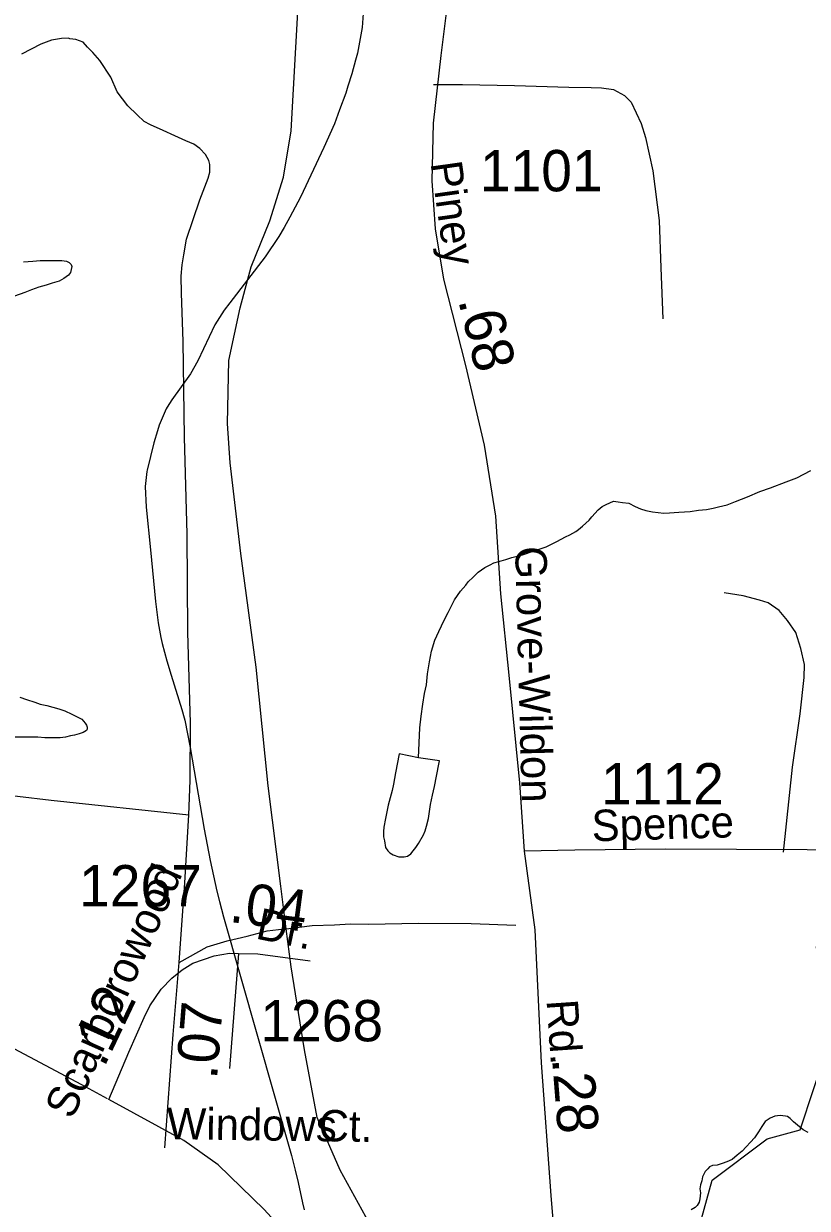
# Model space of a CAD drawing. Extents: x 2001466 to 2224147, y 644118 to 847247.
# Drawn here: x 2046028 to 2048402, y 675296 to 678885 of the extents above; entities that cross this region are included whole.
import ezdxf

# ---------------------------------------------------------------- set-up
doc = ezdxf.new("R2010")
doc.units = 0
for name, color, linetype in [('Exist Hydrographic Misc Water Feature', 7, 'Continuous'), ('Exist Railroad Mainline', 7, 'Continuous'), ('Exist Road Non-System Type 51', 7, 'Continuous'), ('Exist Road Secondary Mileage Hundredths English Label', 7, 'Continuous'), ('Exist Road Secondary Type 51 Attributed', 7, 'Continuous'), ('Exist Road Secondary Type 51 Label', 7, 'Continuous'), ('Exist Road Secondary Type 51 Number Label', 7, 'Continuous')]:
    doc.layers.add(name, color=color, linetype=linetype)

msp = doc.modelspace()

# ---------------------------------------------------------------- linework, layer by layer
at = {"layer": 'Exist Hydrographic Misc Water Feature'}
for p, q in [((2046652.9, 678039.2), (2046635.7, 678016.8)), ((2046463.1, 677723.6), (2046459.8, 677718.3)), ((2046402.8, 677532.5), (2046401.7, 677528.3)), ((2046873, 675313.1), (2046877.7, 675291.8))]:
    msp.add_line(p, q, dxfattribs=at)
for points in [[(2047057.9, 678998.8), (2047058.9, 678944), (2047054, 678873.3), (2047039.7, 678795.8), (2047033.9, 678774.6)], [(2047057.9, 678998.8), (2047058.9, 678944), (2047054, 678873.3), (2047039.7, 678795.8), (2047033.9, 678774.6)], [(2047033.9, 678774.6), (2047022.4, 678732.9), (2047010.5, 678695.5)], [(2047033.9, 678774.6), (2047022.4, 678732.9), (2047010.5, 678695.5)], [(2047010.5, 678695.5), (2047003.8, 678674.5), (2046984.9, 678623.4)], [(2047010.5, 678695.5), (2047003.8, 678674.5), (2046984.9, 678623.4)], [(2046984.9, 678623.4), (2046969.7, 678581.8), (2046937.8, 678510.1)], [(2046984.9, 678623.4), (2046969.7, 678581.8), (2046937.8, 678510.1)], [(2046937.8, 678510.1), (2046866.8, 678359.1), (2046834.6, 678298.9), (2046817, 678267.9)], [(2046937.8, 678510.1), (2046866.8, 678359.1), (2046834.6, 678298.9), (2046817, 678267.9)], [(2046817, 678267.9), (2046800.8, 678239.8), (2046759.8, 678178.1), (2046652.9, 678039.2)], [(2046817, 678267.9), (2046800.8, 678239.8), (2046759.8, 678178.1), (2046652.9, 678039.2)], [(2046027.9, 678163), (2046056, 678165), (2046078, 678167), (2046097.9, 678167.1), (2046114.1, 678167.1), (2046126, 678167.2), (2046144, 678167.2), (2046157.9, 678165.2), (2046165.9, 678161.2), (2046171.9, 678155.2), (2046173.9, 678149.2), (2046170, 678131.2), (2046163.9, 678123.2), (2046150.1, 678113.2), (2046136, 678105.1), (2046114.1, 678099.1), (2046096, 678093.1), (2046074.1, 678087.1), (2046052.1, 678079), (2046032, 678070.9), (2046000.3, 678058.9)], [(2046635.7, 678016.8), (2046607.6, 677972.3), (2046555.7, 677863.1), (2046533.6, 677824.3), (2046476.6, 677745.7), (2046463.1, 677723.6)], [(2046635.7, 678016.8), (2046607.6, 677972.3), (2046555.7, 677863.1), (2046533.6, 677824.3), (2046476.6, 677745.7), (2046463.1, 677723.6)], [(2046459.8, 677718.3), (2046438.7, 677668.7), (2046433.7, 677651.8)], [(2046459.8, 677718.3), (2046438.7, 677668.7), (2046433.7, 677651.8)], [(2046433.7, 677651.8), (2046422.7, 677614.7), (2046402.8, 677532.5)], [(2046433.7, 677651.8), (2046422.7, 677614.7), (2046402.8, 677532.5)], [(2046401.7, 677528.3), (2046396.6, 677482.8), (2046399.7, 677419.9), (2046412.2, 677290.9)], [(2046401.7, 677528.3), (2046396.6, 677482.8), (2046399.7, 677419.9), (2046412.2, 677290.9)], [(2047224.6, 676661.3), (2047228.1, 676751.6), (2047232, 676787.5), (2047237.9, 676823.5), (2047242.1, 676855.3), (2047248.2, 676881.6), (2047252.1, 676915.5), (2047257.6, 676951.5), (2047263.8, 676983.5), (2047273.8, 677017.6), (2047285.7, 677043.4), (2047301.7, 677077.5), (2047313.8, 677101.6), (2047325.5, 677123.3), (2047333.7, 677139.5), (2047351.5, 677165.6), (2047367.3, 677183.5), (2047375.3, 677193.7), (2047389.7, 677207.7), (2047405.5, 677223.6), (2047425.2, 677237.6), (2047441.4, 677245.7), (2047453, 677251.7), (2047467.4, 677256), (2047489.1, 677262), (2047507.2, 677267.8), (2047539.6, 677275.9), (2047575.1, 677287.9), (2047611.1, 677299.9), (2047643.1, 677316.1), (2047669.4, 677330), (2047683.1, 677336), (2047701.4, 677346.2), (2047709.2, 677352.3), (2047721.1, 677362.3), (2047740.9, 677380.4), (2047749.1, 677390.5), (2047768.8, 677412.2), (2047780.7, 677422.2), (2047792.8, 677428.5), (2047815, 677438.5), (2047828.9, 677436.4), (2047842.6, 677434.3), (2047861.1, 677432.3), (2047881, 677422.4), (2047896.8, 677414.7), (2047913.2, 677410.6), (2047932.9, 677406.4), (2047967.1, 677402.5), (2047985, 677402.6), (2048012.8, 677404.8), (2048046.9, 677407), (2048072.9, 677410.7), (2048096.7, 677412.8), (2048117, 677417), (2048133, 677421.1), (2048159, 677426.9), (2048184.9, 677437.2), (2048220.8, 677451.2), (2048258.7, 677467.3), (2048290.9, 677479.1), (2048338.7, 677497.4), (2048370.7, 677509.2), (2048412.7, 677531.6)], [(2046412.2, 677290.9), (2046427.6, 677134.6), (2046435.4, 677070.1), (2046444.2, 677025.1)], [(2046412.2, 677290.9), (2046427.6, 677134.6), (2046435.4, 677070.1), (2046444.2, 677025.1)], [(2046444.2, 677025.1), (2046447.7, 677006.8), (2046461.6, 676954.5), (2046475.2, 676910.9)], [(2046444.2, 677025.1), (2046447.7, 677006.8), (2046461.6, 676954.5), (2046475.2, 676910.9)], [(2046475.2, 676910.9), (2046507.6, 676806.9), (2046514.7, 676781.7)], [(2046475.2, 676910.9), (2046507.6, 676806.9), (2046514.7, 676781.7)], [(2046016.2, 676845.1), (2046036.3, 676837.2), (2046062.4, 676829.3), (2046078.4, 676823.3), (2046098.5, 676819.3), (2046134.4, 676809.4), (2046152.4, 676803.4), (2046174.3, 676793.5), (2046194.4, 676783.5), (2046204.5, 676777.5), (2046214.3, 676765.5), (2046218.4, 676759.5), (2046220.5, 676753.6), (2046220.5, 676747.6), (2046218.6, 676743.6), (2046208.6, 676737.5), (2046196.5, 676733.5), (2046182.5, 676729.5), (2046170.4, 676727.4), (2046154.5, 676723.4), (2046138.5, 676721.4), (2046120.6, 676721.4), (2046108.5, 676721.3), (2046092.5, 676721.3), (2046070.6, 676723.3), (2046034.5, 676723.2), (2046002.5, 676723.1)], [(2046514.7, 676781.7), (2046516.6, 676774.7), (2046532.6, 676692), (2046574.6, 676444.3)], [(2046514.7, 676781.7), (2046516.6, 676774.7), (2046532.6, 676692), (2046574.6, 676444.3)], [(2047224.6, 676661.3), (2047166.2, 676673.4), (2047154.5, 676615.1), (2047148.8, 676581.1), (2047144.7, 676561.5), (2047132.6, 676517.4), (2047124.6, 676477.3), (2047119, 676451.3), (2047118.8, 676437.2), (2047118.6, 676421.4), (2047120.9, 676409.3), (2047124.8, 676389.2), (2047131.3, 676379.3), (2047137.1, 676373.2), (2047147.1, 676367.2), (2047164.7, 676361.3), (2047180.9, 676361.3), (2047191, 676363.4), (2047201, 676369.6), (2047208.6, 676379.4), (2047216.6, 676389.5), (2047224.6, 676401.7), (2047239.2, 676427.5), (2047244.9, 676439.6), (2047248.6, 676453.6), (2047254.8, 676477.4), (2047260.9, 676519.5), (2047266.9, 676547.4), (2047272.4, 676573.7), (2047286.3, 676641.4), (2047288.4, 676651.6), (2047224.6, 676661.3)], [(2046574.6, 676444.3), (2046592.7, 676350.3), (2046613.6, 676257.1), (2046621.8, 676225.4)], [(2046574.6, 676444.3), (2046592.7, 676350.3), (2046613.6, 676257.1), (2046621.8, 676225.4)], [(2046621.8, 676225.4), (2046633.7, 676178.8), (2046839.7, 675456.2), (2046850.4, 675411.8)], [(2046621.8, 676225.4), (2046633.7, 676178.8), (2046839.7, 675456.2), (2046850.4, 675411.8)], [(2048081.5, 675264.4), (2048114.5, 675381.8), (2048280.6, 675506.4), (2048380.7, 675533.9), (2048463.5, 675784.8), (2048463.5, 676024.3), (2048429.7, 676084.1), (2048437.7, 676166), (2048604.6, 676192.1)], [(2048404.5, 675525.9), (2048389.9, 675533.8), (2048372.3, 675547.8), (2048360.4, 675557.8), (2048350.2, 675567.8), (2048342.4, 675573.9), (2048336.2, 675575.6), (2048320.4, 675577.6), (2048304.2, 675575.6), (2048290.1, 675569.6), (2048274.5, 675559.5), (2048264, 675543.6), (2048254.2, 675527.6), (2048242.3, 675509.6), (2048204.6, 675469.4), (2048190.2, 675457.5), (2048174.4, 675443.6), (2048158.4, 675437.5), (2048144.7, 675431.5), (2048128.7, 675427.4), (2048114.8, 675425.5), (2048106.3, 675421.5), (2048100.4, 675415.5), (2048092.6, 675407.3), (2048088.7, 675399.4), (2048084.4, 675391.1), (2048082.4, 675379.3), (2048078.7, 675367.3), (2048076.8, 675355.4), (2048078.5, 675343.3), (2048076.8, 675325.3), (2048074.8, 675315.1), (2048068.8, 675305.1), (2048062.7, 675299.1), (2048050.8, 675291.2)], [(2046850.4, 675411.8), (2046859.6, 675374), (2046873, 675313.1)], [(2046850.4, 675411.8), (2046859.6, 675374), (2046873, 675313.1)]]:
    msp.add_lwpolyline(points, dxfattribs=at)
at = {"layer": 'Exist Railroad Mainline'}
msp.add_lwpolyline([(2047327.9, 674874), (2047221.5, 675019.8), (2047087.4, 675229.7), (2046987.3, 675411.8), (2046917.3, 675571.8), (2046879.1, 675775.8), (2046839, 676027.8), (2046823.8, 676143.3), (2046806.8, 676271.8), (2046768.8, 676576), (2046732.5, 676936), (2046686.3, 677280.1), (2046654.1, 677554.2), (2046646.1, 677674.1), (2046649.6, 677864.9), (2046683.6, 678023.6), (2046717.6, 678148.3), (2046774.2, 678288.1), (2046815.8, 678420.3), (2046838.4, 678560.1), (2046881, 679318.8), (2046890.6, 680593)], dxfattribs=at)
at = {"layer": 'Exist Road Non-System Type 51'}
for points in [[(2046528.4, 676487.9), (2046532.5, 676591.8), (2046534, 676765.8), (2046525.7, 677042), (2046523.7, 677338), (2046515.7, 677632.2), (2046511.6, 677922.2), (2046506.6, 678068.4), (2046505.6, 678120.4), (2046508.3, 678154.3), (2046512.9, 678184.2), (2046521.9, 678232), (2046562.3, 678351.2), (2046587.6, 678416.7), (2046592, 678434.6), (2046592.5, 678458.6), (2046588.7, 678470.7), (2046579.1, 678488.9), (2046561.5, 678507.2), (2046543.7, 678519.6), (2046519.9, 678530.1), (2046486.2, 678544.8), (2046450.6, 678561.5), (2046412.9, 678578.3), (2046393.1, 678588.7), (2046371.6, 678609.1), (2046344.1, 678635.7), (2046311, 678678.3), (2046291.9, 678722.7), (2046258.9, 678773.4), (2046237.4, 678797.8), (2046221.7, 678814.1), (2046208, 678828.4), (2046186.2, 678836.9), (2046168.2, 678839.2), (2046164.3, 678841.3), (2046142.3, 678839.8), (2046112.1, 678834.4), (2046079.9, 678823), (2046021.3, 678792.2)], [(2047269.4, 678700.9), (2047357.4, 678701.1), (2047515.4, 678697.9), (2047679.3, 678692.5), (2047747.2, 678691.2), (2047779.2, 678690.5), (2047815.1, 678685.8), (2047848.7, 678667.1), (2047868.3, 678646.7), (2047883.7, 678614.4), (2047899, 678582.1), (2047912.1, 678539.8), (2047934.1, 678439.4), (2047953, 678289), (2047958.1, 678144.9), (2047965, 677990.7)], [(2048330.1, 676375.3), (2048357.3, 676632.8), (2048380.6, 676794.3), (2048392.8, 676904), (2048393.7, 676944), (2048382.6, 676992.2), (2048367.6, 677040.6), (2048342.4, 677077.1), (2048317, 677107.6), (2048283.5, 677130.3), (2048257.6, 677138.8), (2048207.9, 677151.8), (2048150.1, 677161)], [(2045804, 676568.6), (2046111.3, 676532.4), (2046528.4, 676487.9)], [(2046499.3, 676040.5), (2046516.2, 676282.1), (2046528.4, 676487.9)], [(2046823.8, 676143.3), (2046901.9, 676153.2), (2046969.6, 676154.9), (2047018.8, 676157.8), (2047071.6, 676156.9), (2047225.7, 676159.7), (2047383.7, 676158.5), (2047519.6, 676153.8)], [(2046499.3, 676040.5), (2046584.3, 676088.8), (2046644.5, 676106.3), (2046704.9, 676120.3), (2046766.1, 676136.8), (2046800.1, 676140.4), (2046823.8, 676143.3)], [(2046455.8, 675479.4), (2046480.8, 675822.9), (2046499.3, 676040.5)]]:
    msp.add_lwpolyline(points, dxfattribs=at)
at = {"layer": 'Exist Road Secondary Type 51 Attributed'}
msp.add_line((2046679.1, 676068.4), (2046651.3, 675720.1), dxfattribs=at)
for points in [[(2047258.8, 679934.1), (2047292.1, 679771.4), (2047333.2, 679611.9), (2047364.9, 679453.5), (2047368.6, 679358.4), (2047352.7, 679231.7), (2047316.3, 678983.4), (2047292.1, 678788), (2047268.3, 678583.1), (2047265.1, 678408.8), (2047274.6, 678263), (2047300.5, 678110.9), (2047366.5, 677848.9), (2047423.5, 677608.1), (2047457.3, 677392.6), (2047473.1, 677158.1), (2047498.4, 676910.9), (2047530.1, 676585.6), (2047544.9, 676378.5)], [(2046282.6, 675627.7), (2046203.9, 675670.6), (2044328.5, 676668), (2043917.8, 676900.4), (2043829.2, 676968), (2043789.1, 677039.9), (2043734.2, 677223.7), (2043704.6, 677396.9), (2043652.9, 677538.4), (2043576.9, 677627.2), (2043486.1, 677694.8), (2043338.3, 677760.3), (2043108.3, 677828)], [(2050014.9, 676250.4), (2049922.5, 676279.6), (2049821.1, 676304.7), (2049661.3, 676338.4), (2049443.9, 676370.1), (2049206.4, 676378.5), (2048616.8, 676380.7), (2047972.9, 676383.8), (2047697.9, 676380.7), (2047544.9, 676378.5)], [(2047544.9, 676378.5), (2047576.5, 676139.8), (2047596.1, 675737.4), (2047625.1, 675334.9), (2047648.3, 675053.9), (2047662, 674855.3)], [(2046285.7, 675626), (2046347.1, 675769.6), (2046393.1, 675873.9), (2046410, 675909.5), (2046444.7, 675959.8), (2046476.9, 675993.7), (2046508.1, 676018.9), (2046541.1, 676038.9), (2046605.3, 676061.5), (2046651.3, 676069.3), (2046679.1, 676068.4)], [(2046679.1, 676068.4), (2046737.3, 676066.7), (2046895.7, 676045.8)], [(2047662, 674855.3), (2047249.3, 674876.5), (2047154.3, 674901.8), (2047072, 674954.7), (2046924.2, 675108.9), (2046756.3, 675292.7), (2046617, 675427.9), (2046513.6, 675501.8), (2046285.7, 675626)]]:
    msp.add_lwpolyline(points, dxfattribs=at)

# ---------------------------------------------------------------- texts
at = {"layer": 'Exist Road Secondary Mileage Hundredths English Label'}
for s, rotation, p in [('.68', 283.9025, (2047344, 678047.4)), ('.04', 352.5046, (2046648.4, 676164.3)), ('.12', 64.5752, (2046271.6, 675720)), ('.07', 85.4397, (2046613.6, 675684.8)), ('.28', 274.5761, (2047628.8, 675750.3))]:
    msp.add_text(s, height=125, rotation=rotation, dxfattribs=at).set_placement(p)
at = {"layer": 'Exist Road Secondary Type 51 Label'}
for s, rotation, p in [('Piney', 277.9959, (2047260.5, 678462.5)), ('Grove-Wildon', 271.4767, (2047517.1, 677300.6)), ('Spence', 1.657, (2047750.2, 676407.8)), ('Scarborowood', 65.8649, (2046175.7, 675562.6)), ('Dr.', 348.2194, (2046728, 676114)), ('Rd.', 273.9511, (2047612.1, 675926.1)), ('Windows', 359.1898, (2046461, 675505.9)), ('Ct.', 359.1898, (2046921.4, 675499.6))]:
    msp.add_text(s, height=95, rotation=rotation, dxfattribs=at).set_placement(p)
at = {"layer": 'Exist Road Secondary Type 51 Number Label'}
for s, p in [('1101', (2047410.3, 678377.1)), ('1112', (2047777.7, 676519.8)), ('1267', (2046196.1, 676211)), ('1268', (2046745.2, 675802.1))]:
    msp.add_text(s, height=125, dxfattribs=at).set_placement(p)

doc.saveas('drawing.dxf')
